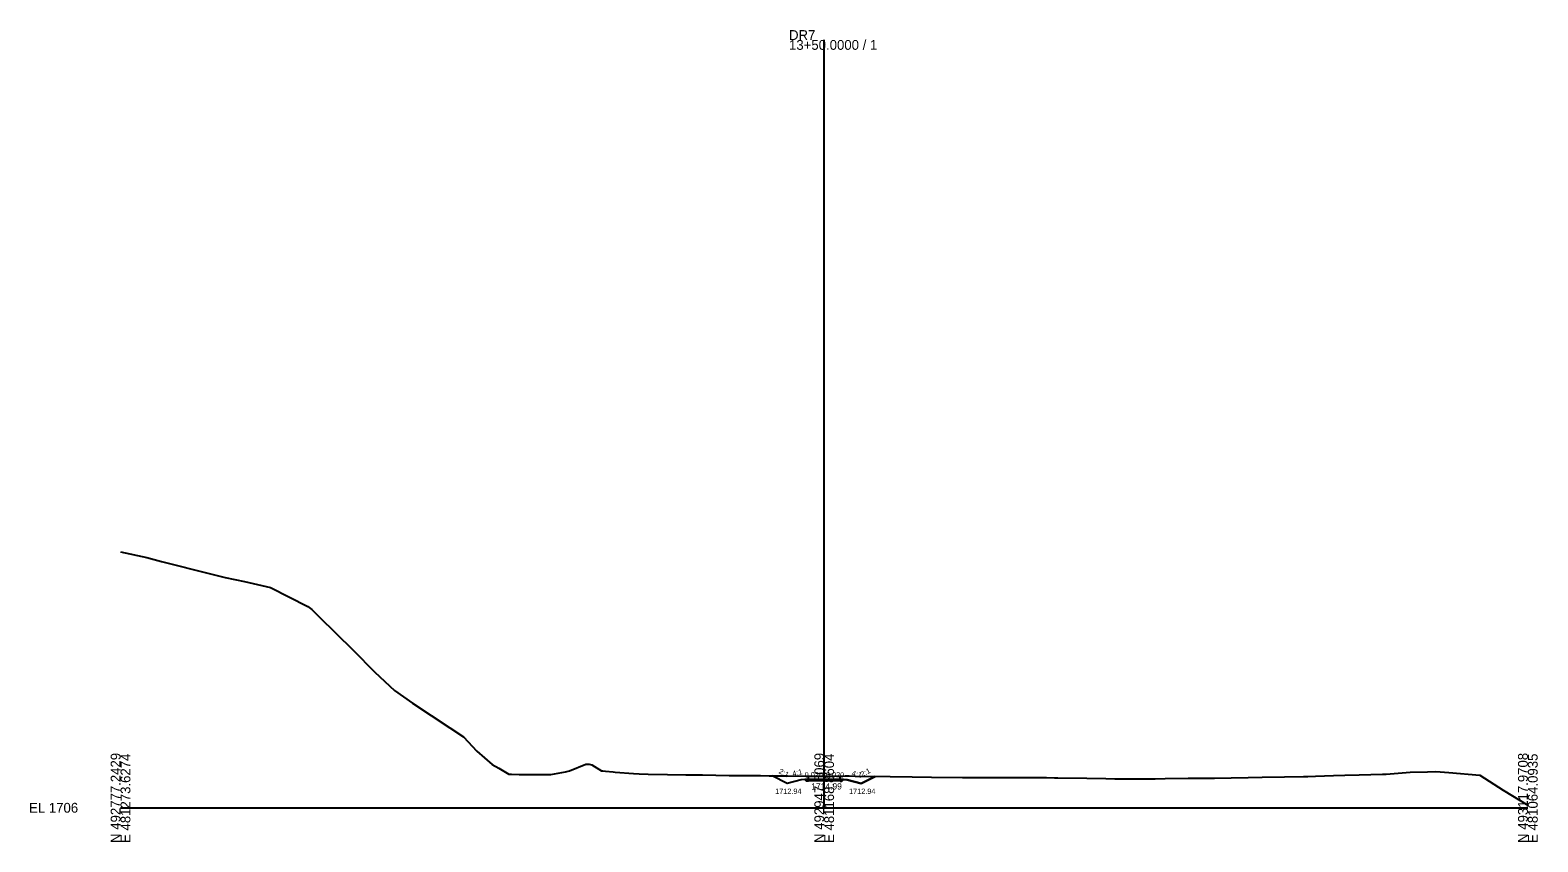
# Model space of a CAD drawing. Extents: x -26 to 403, y -10 to 4215.
# Drawn here: x -25.7 to 402.8, y 3490.3 to 3721.1 of the extents above; entities that cross this region are included whole.
import ezdxf

# ---------------------------------------------------------------- set-up
doc = ezdxf.new("R2010")
doc.units = 0
for name, color, linetype in [('Exist Cross Section Cell', 7, 'Continuous'), ('Exist XS Center Line Elevation Label', 7, 'Continuous'), ('Exist XS Ground Line', 7, 'Continuous'), ('Prop XS Ditch Slope Text', 7, 'Continuous'), ('Prop XS Ditch Standard Text', 7, 'Continuous'), ('Prop XS Dump Level', 7, 'Continuous'), ('Prop XS Earthwork Shape', 7, 'Continuous'), ('Prop XS EOT Tick Mark', 7, 'Continuous'), ('Prop XS Finish Grade', 7, 'Continuous'), ('Prop XS Finish Grade Earthwork', 7, 'Continuous'), ('Prop XS Finish Grade Pavement', 7, 'Continuous'), ('Prop XS Hydro Typical Ditch Data', 7, 'Continuous'), ('Prop XS Pvmt Edge Slope', 7, 'Continuous'), ('Prop XS SE Text', 7, 'Continuous'), ('Prop XS Shoulder Borrow Shape', 7, 'Continuous'), ('Prop XS Side Slope Text', 7, 'Continuous'), ('Prop XS Subgrade Earthwork', 7, 'Continuous')]:
    doc.layers.add(name, color=color, linetype=linetype)

msp = doc.modelspace()

# ---------------------------------------------------------------- linework, layer by layer
at = {"layer": 'Exist Cross Section Cell'}
for p, q in [((200, 3500), (200, 3718.33)), ((0, 3500), (200, 3500)), ((200, 3500), (400, 3500))]:
    msp.add_line(p, q, dxfattribs=at)
at = {"layer": 'Exist XS Ground Line'}
msp.add_lwpolyline([(0, 3572.78), (7.43, 3571.15), (11.65, 3570.07), (25.53, 3566.49), (29.78, 3565.48), (35.27, 3564.32), (42.66, 3562.65), (53.19, 3557.2), (54.4, 3556.34), (56.33, 3554.43), (66.14, 3544.82), (72.29, 3538.54), (77.89, 3533.31), (83.02, 3529.74), (93.62, 3522.75), (97.48, 3520.19), (101.22, 3516.06), (105.61, 3512.35), (107.56, 3511.22), (110.34, 3509.52), (111.12, 3509.53), (113.32, 3509.5), (120.19, 3509.44), (121.26, 3509.43), (121.69, 3509.42), (122.31, 3509.42), (126.44, 3510.23), (127.65, 3510.49), (132.22, 3512.43), (133.18, 3512.37), (133.97, 3512.24), (136.69, 3510.49), (137.12, 3510.48), (137.83, 3510.39), (139.97, 3510.19), (140.58, 3510.09), (145.79, 3509.79), (147.38, 3509.68), (149.93, 3509.57), (155.49, 3509.5), (160.63, 3509.38), (165.42, 3509.35), (172.97, 3509.16), (181.91, 3509.17), (184.33, 3509.11), (189.6, 3509.07), (195.48, 3509), (199.36, 3508.99), (200, 3508.99), (205.94, 3509.05), (207.05, 3509.05), (208.81, 3509.03), (218.79, 3508.87), (225.04, 3508.82), (230.53, 3508.72), (239.3, 3508.65), (242.27, 3508.63), (244.13, 3508.61), (254.01, 3508.57), (263.22, 3508.59), (265.5, 3508.56), (266.44, 3508.54), (274.68, 3508.42), (280.09, 3508.35), (282.56, 3508.26), (287.06, 3508.2), (294.1, 3508.26), (296.94, 3508.28), (303.46, 3508.39), (310.9, 3508.45), (315.69, 3508.56), (320.5, 3508.62), (324.46, 3508.67), (330.79, 3508.76), (336.21, 3508.87), (337.5, 3508.89), (339.6, 3508.96), (344.77, 3509.17), (347.95, 3509.27), (352.04, 3509.41), (358.69, 3509.52), (359.31, 3509.54), (359.69, 3509.57), (366.58, 3510.14), (371.43, 3510.24), (373.85, 3510.34), (377.52, 3510), (386.31, 3509.27), (392.99, 3505.02), (400, 3500.72)], dxfattribs=at)
at = {"layer": 'Prop XS Dump Level'}
for p, q in [((195.5, 3508.1), (200, 3508.19)), ((200, 3508.19), (204.5, 3508.1))]:
    msp.add_line(p, q, dxfattribs=at)
at = {"layer": 'Prop XS Earthwork Shape'}
msp.add_lwpolyline([(194.48, 3508.02), (193.5, 3507.94), (189.5, 3506.94), (185.19, 3509.1), (189.6, 3509.07), (195.48, 3509), (199.36, 3508.99), (200, 3508.99), (205.94, 3509.05), (207.05, 3509.05), (208.81, 3509.03), (214.49, 3508.94), (210.5, 3506.94), (206.5, 3507.94), (205.52, 3508.02), (205.05, 3507.55), (204.5, 3507.56), (200, 3507.65), (195.5, 3507.56), (194.95, 3507.55)], close=True, dxfattribs=at)
at = {"layer": 'Prop XS EOT Tick Mark'}
for p, q in [((195.5, 3508.1), (195.5, 3509.1)), ((204.5, 3508.1), (204.5, 3509.1))]:
    msp.add_line(p, q, dxfattribs=at)
at = {"layer": 'Prop XS Finish Grade'}
for p, q in [((195.5, 3508.1), (194.48, 3508.02)), ((204.5, 3508.1), (205.52, 3508.02))]:
    msp.add_line(p, q, dxfattribs=at)
at = {"layer": 'Prop XS Finish Grade Earthwork'}
for p, q in [((189.5, 3506.94), (185.19, 3509.1)), ((193.5, 3507.94), (189.5, 3506.94)), ((194.48, 3508.02), (193.5, 3507.94)), ((205.52, 3508.02), (206.5, 3507.94)), ((206.5, 3507.94), (210.5, 3506.94)), ((210.5, 3506.94), (214.49, 3508.94))]:
    msp.add_line(p, q, dxfattribs=at)
at = {"layer": 'Prop XS Finish Grade Pavement'}
for p, q in [((195.5, 3508.1), (200, 3508.19)), ((200, 3508.19), (204.5, 3508.1))]:
    msp.add_line(p, q, dxfattribs=at)
at = {"layer": 'Prop XS Hydro Typical Ditch Data'}
for p, q in [((189.5, 3506.94), (185.19, 3509.1)), ((193.5, 3507.94), (189.5, 3506.94)), ((206.5, 3507.94), (210.5, 3506.94)), ((210.5, 3506.94), (214.49, 3508.94))]:
    msp.add_line(p, q, dxfattribs=at)
at = {"layer": 'Prop XS Pvmt Edge Slope'}
for p, q in [((195.5, 3508.1), (194.95, 3507.55)), ((204.5, 3508.1), (205.05, 3507.55))]:
    msp.add_line(p, q, dxfattribs=at)
at = {"layer": 'Prop XS Shoulder Borrow Shape'}
for points in [[(195.5, 3508.1), (194.95, 3507.55), (194.48, 3508.02)], [(195.5, 3508.1), (194.95, 3507.55), (194.48, 3508.02)], [(205.05, 3507.55), (205.52, 3508.02), (204.5, 3508.1)], [(205.05, 3507.55), (205.52, 3508.02), (204.5, 3508.1)]]:
    msp.add_lwpolyline(points, close=True, dxfattribs=at)
at = {"layer": 'Prop XS Subgrade Earthwork'}
for p, q in [((194.95, 3507.55), (194.48, 3508.02)), ((195.5, 3507.56), (194.95, 3507.55)), ((200, 3507.65), (195.5, 3507.56)), ((204.5, 3507.56), (200, 3507.65)), ((204.5, 3507.56), (205.05, 3507.55)), ((205.05, 3507.55), (205.52, 3508.02))]:
    msp.add_line(p, q, dxfattribs=at)

# ---------------------------------------------------------------- texts
at = {"layer": 'Exist Cross Section Cell'}
for s, p in [('DR7', (190, 3718.33)), ('13+50.0000 / 1', (190, 3715.53)), ('EL 1706', (-26, 3498.6))]:
    msp.add_text(s, height=2.8, dxfattribs=at).set_placement(p)
for s, p in [('N 492777.2429', (0, 3490)), ('E 481273.6274', (2.8, 3490)), ('N 492947.6069', (200, 3490)), ('E 481168.8604', (202.8, 3490)), ('N 493117.9708', (400, 3490)), ('E 481064.0935', (402.8, 3490))]:
    msp.add_text(s, height=2.8, rotation=90, dxfattribs=at).set_placement(p)
at = {"layer": 'Exist XS Center Line Elevation Label'}
msp.add_text('1714.99', height=1.8, dxfattribs=at).set_placement((196.32, 3505.19))
at = {"layer": 'Prop XS Ditch Slope Text'}
for rotation, p in [(14.0362, (191.14, 3508.9)), (345.9638, (207.71, 3509.19))]:
    msp.add_text('4:1', height=1.5, rotation=rotation, dxfattribs=at).set_placement(p)
at = {"layer": 'Prop XS Ditch Standard Text'}
for p in [(186.06, 3503.94), (207.06, 3503.94)]:
    msp.add_text('1712.94', height=1.5, dxfattribs=at).set_placement(p)
at = {"layer": 'Prop XS Dump Level'}
for p in [(193.5, 3507.9), (206.5, 3507.9)]:
    msp.add_text('Case1', height=0.04, dxfattribs=at).set_placement(p)
at = {"layer": 'Prop XS SE Text'}
for rotation, p in [(1.1458, (194.47, 3508.6)), (358.8542, (200.48, 3508.7))]:
    msp.add_text('0.020', height=1.5, rotation=rotation, dxfattribs=at).set_placement(p)
at = {"layer": 'Prop XS Side Slope Text'}
for rotation, p in [(333.4349, (186.95, 3509.9)), (26.5651, (210.76, 3508.75))]:
    msp.add_text('2:1', height=1.5, rotation=rotation, dxfattribs=at).set_placement(p)

doc.saveas('drawing.dxf')
